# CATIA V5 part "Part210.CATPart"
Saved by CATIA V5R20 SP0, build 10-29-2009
Part number: IA 1007SF
Revision: ANY
Definition: UNKNOWN
Nomenclature: IA 1007SF
Source: Unknown
Bounding box of the stored display mesh (mm): x -5.35 to 5.35, y -17 to 0, z -5.35 to 5.35
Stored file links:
  C:\Users\Utente\Desktop\IO LAVORO\3D X SITO CF\CUMSA\3D files FA\FA 200700\Part210.CATPart
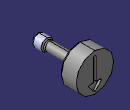
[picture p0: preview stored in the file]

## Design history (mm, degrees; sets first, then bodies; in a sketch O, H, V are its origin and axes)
Body1 "Cortar-Extruir1" (main body)
  Solid1: solid without history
